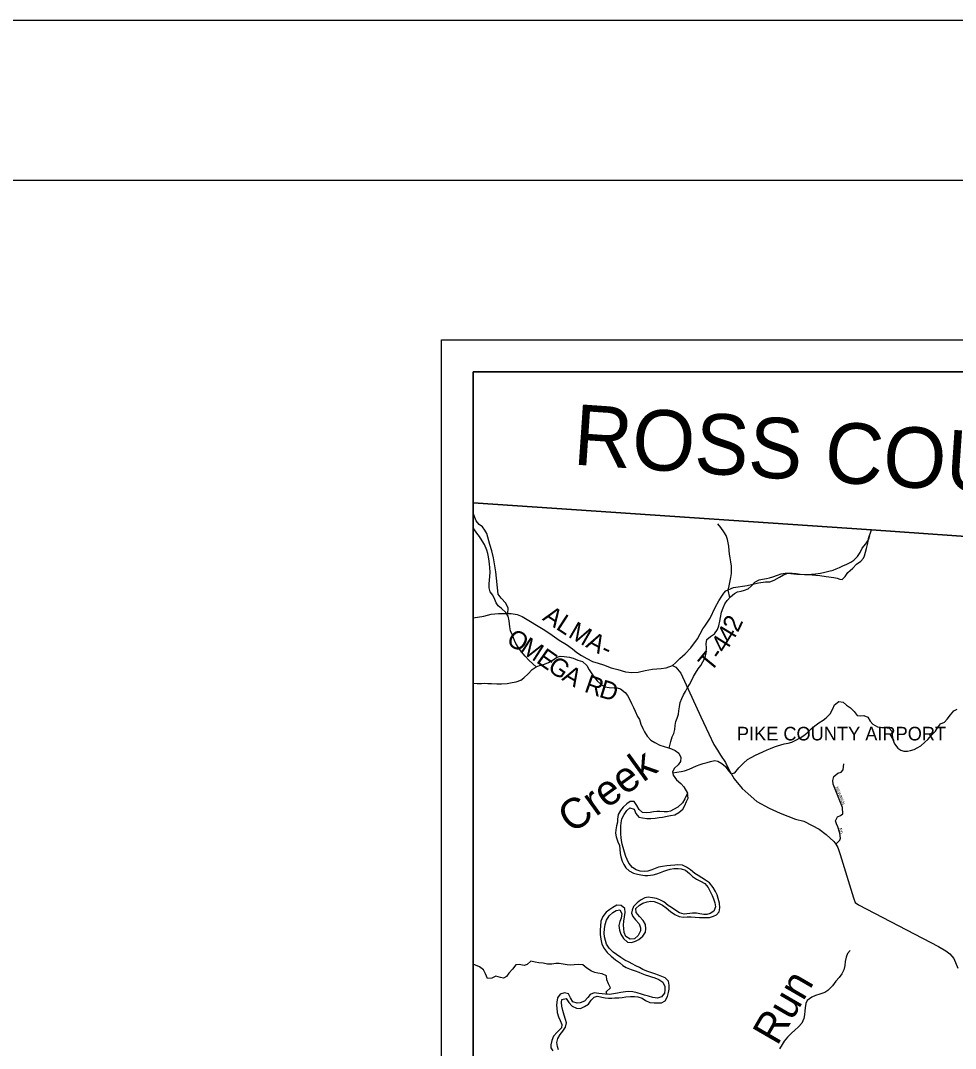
# Model space of a CAD drawing. Extents: x 0 to 34, y 0 to 22.
# Drawn here: x 22.598 to 25.527, y 18.782 to 22 of the extents above; entities that cross this region are included whole.
import ezdxf

# ---------------------------------------------------------------- set-up
doc = ezdxf.new("R2010")
doc.units = 0
for name, color, linetype in [('GM_X_Adjacent_County', 7, 'Continuous'), ('GM_X_Adjacent_County_Text', 7, 'Continuous'), ('GM_X_Airport_Text_Class_3', 7, 'Continuous'), ('GM_X_County', 7, 'Continuous'), ('GM_X_County_Road', 7, 'Continuous'), ('GM_X_County_Road_Text', 7, 'Continuous'), ('GM_X_Minor_River', 7, 'Continuous'), ('GM_X_Minor_River_Text', 7, 'Continuous'), ('GM_X_Township', 7, 'Continuous'), ('GM_X_Township_Road', 7, 'Continuous'), ('GM_X_Township_Road_Text', 7, 'Continuous'), ('GM_X_Township_Subdivision', 7, 'Continuous'), ('GM_X_Township_Subdivision_Text', 7, 'Continuous'), ('SH_Border', 7, 'Continuous'), ('SH_Cut_Line', 7, 'Continuous'), ('SH_Data', 7, 'Continuous')]:
    doc.layers.add(name, color=color, linetype=linetype)

msp = doc.modelspace()

# ---------------------------------------------------------------- linework, layer by layer
at = {"layer": 'GM_X_Adjacent_County'}
for points in [[(30.8167, 19.9966), (30.8167, 20.9), (24.0167, 20.9), (24.0167, 20.4902)], [(24.0167, 20.4902), (25.2637, 20.4053), (26.0476, 20.3502), (26.2222, 20.3325), (27.8816, 20.224), (28.5075, 20.1657), (30.3764, 20.0297), (30.5069, 20.0201), (30.8167, 19.9966)]]:
    msp.add_lwpolyline(points, dxfattribs=at)
at = {"layer": 'GM_X_County'}
for points in [[(24.0167, 20.4902), (24.0167, 14.1), (30.8167, 14.1), (30.8167, 19.9966)], [(30.8167, 19.9966), (30.5069, 20.0201), (30.3764, 20.0297), (28.5075, 20.1657), (27.8816, 20.224), (26.2222, 20.3325), (26.0476, 20.3502), (25.2637, 20.4053), (24.0167, 20.4902)]]:
    msp.add_lwpolyline(points, dxfattribs=at)
at = {"layer": 'GM_X_County_Road'}
msp.add_lwpolyline([(24.0167, 20.1298), (24.0491, 20.1354), (24.0722, 20.1414), (24.0955, 20.1436), (24.1114, 20.1436), (24.1248, 20.1434), (24.1353, 20.1433), (24.154, 20.1406), (24.1699, 20.134), (24.2409, 20.0919), (24.2635, 20.0755), (24.2854, 20.0602), (24.3084, 20.0468), (24.3269, 20.0334), (24.3412, 20.0216), (24.3556, 20.0128), (24.3726, 20.0028), (24.3903, 19.994), (24.4073, 19.9882), (24.4247, 19.9832), (24.4482, 19.9736), (24.4697, 19.9682), (24.4936, 19.9608), (24.5132, 19.9592), (24.5333, 19.9606), (24.5546, 19.9655), (24.5784, 19.9699), (24.6053, 19.9717), (24.6209, 19.9739), (24.6402, 19.9813), (24.6512, 19.9756), (24.667, 19.9569), (24.7295, 19.8204), (24.7539, 19.7675), (24.7704, 19.734), (24.782, 19.7157), (24.7914, 19.7001), (24.8061, 19.6776), (24.8177, 19.6529), (24.8338, 19.6259), (24.8587, 19.5962), (24.8771, 19.5794), (24.9047, 19.5557), (24.9436, 19.5339), (24.9776, 19.5185), (25.0256, 19.5004), (25.0517, 19.4938), (25.0785, 19.4804), (25.0996, 19.4689), (25.1219, 19.4521), (25.146, 19.4304), (25.152, 19.4216), (25.1588, 19.4117), (25.1655, 19.3896), (25.2076, 19.2532), (25.2124, 19.2391), (25.223, 19.2315), (25.4742, 19.1015), (25.4964, 19.0881), (25.5089, 19.0789), (25.5213, 19.0641), (25.5348, 19.0333)], dxfattribs=at)
at = {"layer": 'GM_X_Minor_River'}
for points in [[(24.2138, 19.9765), (24.192, 19.9965), (24.1793, 20.0103), (24.1677, 20.0234), (24.1572, 20.0379), (24.1502, 20.0494), (24.1454, 20.0597), (24.1399, 20.0757), (24.1336, 20.0898), (24.1307, 20.102), (24.1294, 20.1209), (24.1254, 20.135), (24.1187, 20.1465), (24.1052, 20.1596), (24.0947, 20.168), (24.0887, 20.1776), (24.0843, 20.1875), (24.078, 20.2009), (24.0698, 20.212), (24.0665, 20.2241), (24.0667, 20.2363), (24.0676, 20.2477), (24.0688, 20.2598), (24.069, 20.2727), (24.0688, 20.2879), (24.0674, 20.2985), (24.0664, 20.308), (24.0643, 20.3217), (24.0617, 20.3316), (24.0588, 20.3423), (24.0518, 20.3598), (24.0444, 20.3717), (24.0358, 20.385), (24.028, 20.3954), (24.0186, 20.4084), (24.0167, 20.4111)], [(24.82, 20.1938), (24.8154, 20.2168), (24.8179, 20.2308), (24.8211, 20.2456), (24.8231, 20.2566), (24.8252, 20.2691), (24.8257, 20.2789), (24.8254, 20.2922), (24.8233, 20.3055), (24.8208, 20.3181), (24.8194, 20.3291), (24.8184, 20.3405), (24.8174, 20.3546), (24.8131, 20.3751), (24.8084, 20.3881), (24.8017, 20.3999), (24.7924, 20.4126), (24.7826, 20.4248)], [(24.6299, 19.7226), (24.6352, 19.7436), (24.6395, 19.758), (24.6446, 19.7682), (24.6477, 19.7807), (24.649, 19.7932), (24.6514, 19.8057), (24.655, 19.8166), (24.6589, 19.8291), (24.6609, 19.8393), (24.6622, 19.8515), (24.665, 19.8647), (24.6697, 19.878), (24.6755, 19.8897), (24.6817, 19.8998), (24.686, 19.9097), (24.6933, 19.9217), (24.6999, 19.9327), (24.7065, 19.9466), (24.7127, 19.9572), (24.7212, 19.9704), (24.7297, 19.9813), (24.7355, 19.9922), (24.7425, 20.0058), (24.7457, 20.021), (24.7466, 20.0358), (24.7464, 20.049), (24.7484, 20.0627), (24.7595, 20.0717), (24.7721, 20.0799), (24.7818, 20.0942), (24.7857, 20.1048), (24.7893, 20.1203), (24.7909, 20.1317), (24.7942, 20.1476), (24.7989, 20.1619), (24.8047, 20.1737), (24.812, 20.1846), (24.822, 20.1962), (24.8343, 20.2067), (24.8442, 20.2112), (24.8552, 20.2141), (24.8662, 20.2166), (24.8773, 20.221), (24.8872, 20.2297), (24.8988, 20.2421), (24.9121, 20.2491), (24.9227, 20.2513), (24.9345, 20.2534), (24.9448, 20.2556), (24.9547, 20.2581), (24.9699, 20.2636), (24.9809, 20.2677), (24.9938, 20.2702), (25.0056, 20.2705), (25.0155, 20.27), (25.0283, 20.2687), (25.0401, 20.267), (25.0537, 20.2661), (25.0666, 20.266), (25.0764, 20.2666), (25.0886, 20.268), (25.1038, 20.2705), (25.1178, 20.273), (25.13, 20.2763), (25.1441, 20.2799), (25.1536, 20.2836), (25.1635, 20.288), (25.1745, 20.2928), (25.1867, 20.2984), (25.1989, 20.3043), (25.2085, 20.3107), (25.22, 20.322), (25.2281, 20.3351), (25.2351, 20.3484), (25.2462, 20.3619), (25.2547, 20.3747), (25.2591, 20.3883)], [(24.0167, 19.9261), (24.0176, 19.926), (24.029, 19.9251), (24.0426, 19.925), (24.0521, 19.9252), (24.0623, 19.9247), (24.0737, 19.9246), (24.09, 19.9237), (24.1051, 19.9231), (24.1226, 19.9244), (24.1385, 19.9273), (24.1514, 19.9302), (24.1651, 19.9353), (24.1751, 19.9428), (24.1881, 19.9548), (24.2012, 19.9687), (24.2138, 19.9765), (24.224, 19.981), (24.2392, 19.985), (24.2526, 19.9901), (24.2652, 19.9972), (24.2793, 20.0069), (24.2892, 20.0102), (24.3009, 20.0093), (24.3184, 20.0076), (24.3297, 20.0037), (24.3444, 19.9978), (24.3584, 19.9935), (24.3726, 19.9815), (24.38, 19.9674)], [(24.38, 19.9674), (24.3882, 19.9552), (24.3957, 19.9448), (24.4047, 19.9334), (24.4159, 19.9222), (24.4287, 19.9145), (24.4419, 19.9117), (24.4578, 19.9107), (24.4673, 19.9106), (24.4779, 19.9075), (24.4918, 19.8963), (24.4993, 19.8867), (24.5059, 19.8753), (24.5122, 19.8623), (24.5182, 19.8493), (24.5237, 19.8379), (24.5307, 19.8215), (24.5367, 19.8115), (24.5414, 19.7978), (24.5477, 19.7837), (24.5529, 19.7738), (24.5611, 19.7596), (24.5727, 19.7474), (24.5851, 19.74), (24.6006, 19.7319), (24.6149, 19.7279), (24.6281, 19.7232), (24.6379, 19.72), (24.6489, 19.7154), (24.6605, 19.7065), (24.6668, 19.6935), (24.6659, 19.6803), (24.6586, 19.6701), (24.6467, 19.6596), (24.6401, 19.6479), (24.6423, 19.6376), (24.6535, 19.6231), (24.6662, 19.6116), (24.676, 19.6012), (24.6872, 19.5816)], [(24.6406, 19.6455), (24.6678, 19.6487), (24.6781, 19.6516), (24.6929, 19.6568), (24.704, 19.6612), (24.7154, 19.6672), (24.7272, 19.6708), (24.7367, 19.6741), (24.7496, 19.6778), (24.7599, 19.6807), (24.7732, 19.6832), (24.783, 19.6816), (24.7951, 19.6746), (24.8063, 19.6646), (24.816, 19.6516), (24.8239, 19.642), (24.8353, 19.6449), (24.8487, 19.6607), (24.8625, 19.6754), (24.8756, 19.6866), (24.887, 19.6933), (24.9004, 19.7004), (24.9118, 19.7059), (24.924, 19.7103), (24.9373, 19.717), (24.948, 19.7207), (24.9602, 19.7259), (24.9697, 19.7299), (24.9799, 19.7325), (24.9902, 19.7354), (25.0031, 19.7383), (25.0145, 19.7412), (25.0271, 19.7471), (25.0401, 19.7542), (25.0519, 19.762), (25.0623, 19.7703), (25.0745, 19.7823), (25.086, 19.792), (25.0986, 19.8017), (25.112, 19.8096), (25.1219, 19.8174), (25.1346, 19.8302), (25.1431, 19.8449), (25.1478, 19.8581), (25.1612, 19.8686), (25.1748, 19.8658), (25.1861, 19.8569), (25.1977, 19.8488), (25.2101, 19.8369), (25.2187, 19.8247), (25.2308, 19.8238), (25.2403, 19.8248), (25.2523, 19.819), (25.2598, 19.8071), (25.2676, 19.7975), (25.2827, 19.789), (25.2959, 19.7873), (25.3065, 19.7868), (25.319, 19.7852), (25.3276, 19.7756), (25.329, 19.763), (25.3307, 19.749), (25.3362, 19.7353), (25.3459, 19.7222), (25.3557, 19.7157), (25.3655, 19.7129), (25.3765, 19.7132), (25.3864, 19.7146), (25.3974, 19.7179), (25.407, 19.7231), (25.418, 19.7298), (25.4307, 19.7406), (25.4402, 19.7496), (25.4525, 19.7643), (25.4648, 19.7755), (25.4702, 19.7857), (25.4802, 19.7981), (25.4928, 19.8033), (25.5013, 19.8131), (25.5109, 19.8266), (25.522, 19.8387), (25.5327, 19.8446)], [(24.6872, 19.5816), (24.6793, 19.5636), (24.6716, 19.5508), (24.6574, 19.5376), (24.6441, 19.5298), (24.6345, 19.5254), (24.625, 19.5232), (24.6144, 19.5226), (24.6012, 19.5235), (24.5917, 19.5236), (24.5807, 19.5226), (24.5701, 19.5212), (24.5598, 19.5198), (24.5469, 19.5211), (24.5361, 19.5307), (24.5286, 19.5429), (24.52, 19.5548), (24.5075, 19.5557), (24.498, 19.5482), (24.4865, 19.5377), (24.4773, 19.5272), (24.4699, 19.5143), (24.4682, 19.4996), (24.4681, 19.4901), (24.4654, 19.4795), (24.4626, 19.4662), (24.4624, 19.456), (24.4638, 19.445), (24.4697, 19.4293), (24.4741, 19.4175), (24.4759, 19.4057), (24.4769, 19.3921), (24.4783, 19.3818), (24.483, 19.3681), (24.4882, 19.3585), (24.4945, 19.3474), (24.505, 19.3378), (24.5182, 19.3312), (24.5311, 19.3273), (24.5413, 19.3253), (24.5541, 19.3236), (24.5636, 19.3235), (24.5803, 19.3256), (24.5917, 19.3289), (24.6031, 19.3325), (24.6138, 19.337), (24.6233, 19.3403), (24.6336, 19.3432), (24.6446, 19.345), (24.6579, 19.3456), (24.6677, 19.3447), (24.6817, 19.3404), (24.6941, 19.33), (24.7027, 19.32), (24.7155, 19.3119), (24.7287, 19.3057), (24.7418, 19.2983), (24.7519, 19.2864), (24.7601, 19.2715), (24.7649, 19.2609), (24.7693, 19.2506), (24.7734, 19.2384), (24.7755, 19.2258), (24.7704, 19.2122), (24.7582, 19.2048), (24.7479, 19.2018), (24.7384, 19.2012), (24.726, 19.2036), (24.7161, 19.2052), (24.7036, 19.2058), (24.6771, 19.203), (24.6627, 19.207), (24.6514, 19.214), (24.6371, 19.2232), (24.6274, 19.2302), (24.6131, 19.2413), (24.6006, 19.2479), (24.5908, 19.2518), (24.5784, 19.2539), (24.5644, 19.2556), (24.5541, 19.2538), (24.5404, 19.246), (24.5297, 19.2381), (24.5185, 19.2269), (24.5142, 19.2155), (24.5122, 19.2057), (24.5159, 19.1954), (24.5245, 19.1847), (24.5365, 19.1724), (24.5401, 19.1598), (24.54, 19.1499), (24.5334, 19.136), (24.5215, 19.1255), (24.5075, 19.1245), (24.4943, 19.1323), (24.4888, 19.1456), (24.4878, 19.1578), (24.4872, 19.1676), (24.4877, 19.1805), (24.4905, 19.1945), (24.4926, 19.2078)], [(24.4819, 19.2049), (24.4795, 19.1905), (24.4755, 19.1791), (24.4727, 19.1667), (24.4749, 19.1526), (24.4789, 19.14), (24.4871, 19.1259), (24.4994, 19.1151), (24.5119, 19.1138), (24.5249, 19.1182), (24.5352, 19.1234), (24.5474, 19.1332), (24.5555, 19.1464), (24.5575, 19.1562), (24.5565, 19.1703), (24.5484, 19.1825), (24.5367, 19.1948), (24.5267, 19.2074), (24.526, 19.2203), (24.5375, 19.2304), (24.5478, 19.2371), (24.5608, 19.2416), (24.5729, 19.2429), (24.5835, 19.2421), (24.5964, 19.2374), (24.6088, 19.2304), (24.6208, 19.2227), (24.6347, 19.2107), (24.6479, 19.2018), (24.6614, 19.1949), (24.6747, 19.1936), (24.6868, 19.1938), (24.6986, 19.1937), (24.7111, 19.1928), (24.7247, 19.1919), (24.7436, 19.1924), (24.7562, 19.1926), (24.7687, 19.1959), (24.7782, 19.2), (24.7871, 19.2101), (24.7891, 19.2226), (24.7877, 19.2367), (24.7841, 19.2512), (24.7801, 19.263), (24.7757, 19.2733), (24.7682, 19.2863), (24.7563, 19.3008), (24.7435, 19.3089), (24.7329, 19.3166), (24.7209, 19.324), (24.7107, 19.3302), (24.6972, 19.341), (24.6848, 19.3498), (24.6716, 19.3557), (24.6572, 19.3574), (24.6474, 19.3563), (24.6348, 19.3546), (24.6223, 19.3536), (24.6094, 19.3522), (24.5969, 19.3493), (24.5866, 19.3453), (24.5763, 19.3416), (24.5634, 19.3376), (24.5535, 19.3358), (24.5395, 19.3371), (24.5271, 19.3418), (24.5158, 19.3483), (24.5042, 19.3618), (24.499, 19.3736), (24.4949, 19.3831), (24.4902, 19.3968), (24.4858, 19.4113), (24.4833, 19.422), (24.4804, 19.433), (24.4793, 19.4429), (24.4791, 19.4528), (24.4792, 19.4657), (24.479, 19.4782), (24.4795, 19.488), (24.4823, 19.5009), (24.4889, 19.5145), (24.4974, 19.5269), (24.5073, 19.5356), (24.5202, 19.5312), (24.5253, 19.5175), (24.5346, 19.506), (24.5464, 19.504), (24.5604, 19.5019), (24.5729, 19.5018), (24.5862, 19.5035), (24.5983, 19.5053), (24.6093, 19.5067), (24.6237, 19.5092), (24.6348, 19.5113), (24.6477, 19.5138), (24.6606, 19.5209), (24.6733, 19.5314), (24.6795, 19.5427), (24.6849, 19.5552), (24.69, 19.5661), (24.6872, 19.5816)], [(24.4926, 19.2078), (24.4908, 19.2207), (24.4795, 19.2296), (24.4667, 19.2309), (24.4533, 19.2234), (24.4438, 19.2167), (24.4327, 19.2092), (24.4223, 19.1957), (24.4157, 19.1806), (24.4147, 19.1647), (24.4139, 19.1533), (24.4145, 19.1404), (24.4147, 19.1309), (24.4169, 19.1187), (24.4194, 19.1084), (24.4264, 19.0951), (24.4362, 19.0824), (24.4485, 19.0709), (24.4624, 19.0594), (24.4741, 19.0509), (24.4853, 19.042), (24.4959, 19.0355), (24.5106, 19.0292), (24.5238, 19.0249), (24.5351, 19.021), (24.5449, 19.0167), (24.5551, 19.0128), (24.5653, 19.01), (24.5751, 19.0065), (24.5853, 19.0037), (24.5974, 18.9982), (24.6102, 18.9897), (24.6161, 18.9764), (24.6167, 18.9654), (24.6151, 18.9555), (24.6066, 18.9435), (24.5933, 18.9398), (24.5789, 18.9415), (24.565, 18.9458), (24.5533, 18.949), (24.5431, 18.9522), (24.5298, 18.9561), (24.5159, 18.9593), (24.503, 18.9602), (24.4935, 18.9596), (24.4787, 18.9578), (24.4681, 18.9557), (24.4559, 18.9528), (24.4434, 18.9507), (24.4305, 18.9519), (24.4199, 18.9532), (24.4097, 18.9545), (24.3957, 18.9561), (24.3827, 18.951), (24.375, 18.9412), (24.3654, 18.9299), (24.3517, 18.9248), (24.3415, 18.9237), (24.3283, 18.9277), (24.3212, 18.9407), (24.3153, 18.9536), (24.3024, 18.9564), (24.2891, 18.9524), (24.2803, 18.9408), (24.2779, 18.9275), (24.2774, 18.918), (24.2784, 18.9078), (24.2798, 18.8948), (24.2838, 18.8815), (24.2882, 18.8701), (24.2941, 18.8571), (24.2925, 18.8469), (24.2798, 18.8334), (24.2679, 18.8202), (24.2628, 18.8074), (24.2597, 18.7937), (24.2599, 18.7843), (24.2655, 18.7747)], [(24.283, 18.7783), (24.2804, 18.7882), (24.2787, 18.8007), (24.2819, 18.8132), (24.2888, 18.826), (24.2973, 18.8366), (24.3058, 18.8486), (24.3086, 18.8623), (24.3057, 18.8729), (24.3016, 18.8862), (24.2969, 18.9007), (24.294, 18.9148), (24.2926, 18.9262), (24.2939, 18.9357), (24.3072, 18.9386), (24.3154, 18.9256), (24.3266, 18.9148), (24.3398, 18.9078), (24.3523, 18.9077), (24.3652, 18.9136), (24.3778, 18.9203), (24.3859, 18.9335), (24.3955, 18.9432), (24.405, 18.9454), (24.4292, 18.9406), (24.4406, 18.9393), (24.4501, 18.9392), (24.4603, 18.9402), (24.4721, 18.9408), (24.4827, 18.9419), (24.4948, 18.944), (24.5089, 18.945), (24.5214, 18.9445), (24.5316, 18.9436), (24.5456, 18.9396), (24.5565, 18.9327), (24.5697, 18.9261), (24.5829, 18.9251), (24.6057, 18.9249), (24.6171, 18.9312), (24.6244, 18.9444), (24.6284, 18.9576), (24.63, 18.9679), (24.6305, 18.98), (24.628, 18.9926), (24.6172, 19.0037), (24.6074, 19.0076), (24.5964, 19.0115), (24.5851, 19.0158), (24.573, 19.0198), (24.5606, 19.0237), (24.5477, 19.0292), (24.5372, 19.0354), (24.5255, 19.0412), (24.5146, 19.0474), (24.5048, 19.052), (24.4916, 19.059), (24.4788, 19.0668), (24.4649, 19.0768), (24.4551, 19.0837), (24.4424, 19.096), (24.4338, 19.1083), (24.4302, 19.1205), (24.4276, 19.1319), (24.4262, 19.1429), (24.4272, 19.1565), (24.4292, 19.1706), (24.4339, 19.1842), (24.4424, 19.1974), (24.4539, 19.2082), (24.4638, 19.2138), (24.476, 19.216), (24.4819, 19.2049)], [(25.1976, 19.0893), (25.1892, 19.0791), (25.1841, 19.0682), (25.1809, 19.0549), (25.18, 19.0421), (25.1772, 19.028), (25.1706, 19.016), (25.1625, 19.0047), (25.1518, 18.9923), (25.1418, 18.978), (25.1276, 18.9633), (25.1177, 18.9577), (25.102, 18.9522), (25.088, 18.9478), (25.0773, 18.943), (25.0628, 18.9326), (25.0581, 18.9228), (25.0561, 18.9091), (25.0556, 18.8996), (25.0543, 18.8879), (25.0523, 18.8761), (25.0461, 18.8618), (25.0357, 18.8498), (25.0242, 18.8396), (25.0135, 18.8299), (25.0012, 18.8175), (24.9908, 18.8051), (24.9839, 18.7946), (24.9758, 18.7806)], [(24.4355, 18.9514), (24.4332, 18.9591), (24.4459, 18.9715), (24.4396, 18.9841), (24.4348, 18.9974), (24.4338, 19.0096), (24.4206, 19.0162), (24.407, 19.0175), (24.3968, 19.0203), (24.387, 19.0238), (24.3723, 19.0338), (24.3595, 19.0435), (24.3463, 19.0455), (24.3323, 19.0438), (24.322, 19.0428), (24.3103, 19.0436), (24.2982, 19.0461), (24.2853, 19.0477), (24.2755, 19.0486), (24.2625, 19.0465), (24.2489, 19.0463), (24.2357, 19.0494), (24.2217, 19.0507), (24.2107, 19.052), (24.1971, 19.0556), (24.1852, 19.0455), (24.1757, 19.0418), (24.1602, 19.0446), (24.15, 19.0436), (24.1396, 19.0304), (24.1284, 19.0176), (24.1207, 19.0079), (24.1112, 19.0019), (24.1014, 19.0043), (24.0874, 19.0083), (24.0744, 19.0019), (24.0608, 19.001), (24.0549, 19.0155), (24.049, 19.028), (24.0358, 19.0381), (24.023, 19.0424), (24.0167, 19.0462)]]:
    msp.add_lwpolyline(points, dxfattribs=at)
at = {"layer": 'GM_X_Township'}
msp.add_line((24.0167, 20.4902), (24.0167, 17.2008), dxfattribs=at)
msp.add_lwpolyline([(30.8167, 19.9966), (30.5069, 20.0201), (30.3764, 20.0297), (28.5075, 20.1657), (27.8816, 20.224), (26.2222, 20.3325), (26.0476, 20.3502), (25.2637, 20.4053), (24.0167, 20.4902)], dxfattribs=at)
at = {"layer": 'GM_X_Township_Road'}
for points in [[(24.1248, 20.1434), (24.1257, 20.1608), (24.1186, 20.1757), (24.1039, 20.1921), (24.0949, 20.2046), (24.0869, 20.2745), (24.0795, 20.3182), (24.0743, 20.3402), (24.0688, 20.3603), (24.0585, 20.3941), (24.0526, 20.4049), (24.0458, 20.4147), (24.035, 20.4222), (24.0254, 20.4341), (24.021, 20.4442), (24.0174, 20.4555), (24.0167, 20.4607)], [(24.6402, 19.9813), (24.6497, 19.9889), (24.6638, 20.0029), (24.6806, 20.018), (24.6984, 20.0361), (24.7187, 20.0644), (24.7355, 20.0955), (24.7416, 20.1046), (24.7588, 20.1288), (24.7741, 20.1625), (24.7859, 20.1833), (24.7947, 20.1984), (24.8012, 20.2071), (24.8077, 20.2147), (24.832, 20.2252), (24.8744, 20.2318), (24.9101, 20.2403), (24.9321, 20.2433), (24.9457, 20.2432), (24.959, 20.2484), (24.9757, 20.2578), (24.9886, 20.265), (25.0019, 20.2699), (25.0303, 20.2667), (25.0655, 20.2661), (25.1018, 20.2625), (25.1219, 20.2598), (25.1457, 20.257), (25.1563, 20.2539), (25.1646, 20.2512), (25.1715, 20.2504), (25.181, 20.2595), (25.1901, 20.272), (25.197, 20.2788), (25.2054, 20.2852), (25.2173, 20.2981), (25.2304, 20.3077), (25.2385, 20.3175), (25.2418, 20.3241), (25.2447, 20.336), (25.2478, 20.3472), (25.252, 20.3642), (25.2544, 20.3787), (25.2637, 20.4053)]]:
    msp.add_lwpolyline(points, dxfattribs=at)
at = {"layer": 'GM_X_Township_Subdivision'}
msp.add_lwpolyline([(25.152, 19.4216), (25.165, 19.4337), (25.1665, 19.4409), (25.1647, 19.4561), (25.1583, 19.4758), (25.1546, 19.4857), (25.1516, 19.4945), (25.157, 19.5077), (25.1669, 19.5115), (25.1737, 19.5167), (25.173, 19.5369), (25.1443, 19.6095), (25.1424, 19.6209), (25.1455, 19.6338), (25.1588, 19.6436), (25.1694, 19.6473), (25.1752, 19.6549), (25.1775, 19.6727)], dxfattribs=at)
at = {"layer": 'SH_Border'}
msp.add_lwpolyline([(2, 21.5), (33.5, 21.5), (33.5, 0.5), (2, 0.5)], close=True, dxfattribs=at)
at = {"layer": 'SH_Cut_Line'}
msp.add_lwpolyline([(0, 0), (34, 0), (34, 22), (0, 22)], close=True, dxfattribs=at)
at = {"layer": 'SH_Data'}
for points in [[(23.9167, 21), (30.9167, 21), (30.9167, 14), (23.9167, 14)], [(24.0167, 20.9), (30.8167, 20.9), (30.8167, 14.1), (24.0167, 14.1)]]:
    msp.add_lwpolyline(points, close=True, dxfattribs=at)

# ---------------------------------------------------------------- texts
at = {"layer": 'GM_X_Adjacent_County_Text'}
msp.add_text('ROSS COUNTY', height=0.189394, rotation=356.0927, dxfattribs=at).set_placement((24.3263, 20.6104))
at = {"layer": 'GM_X_Airport_Text_Class_3'}
msp.add_text('PIKE COUNTY AIRPORT', height=0.042614, rotation=0, dxfattribs=at).set_placement((24.8422, 19.7464))
at = {"layer": 'GM_X_County_Road_Text'}
for s, rotation, p in [('A', 326.312, (24.2305, 20.125)), ('L', 326.989, (24.2727, 20.0969)), ('M', 330.0316, (24.3111, 20.072)), ('O', 329.2624, (24.117, 20.0506)), ('A', 331.6923, (24.3661, 20.0403)), ('M', 327.2955, (24.1595, 20.0253)), ('E', 325.0273, (24.2109, 19.9923)), ('-', 334.2406, (24.4126, 20.0154)), ('G', 325.3654, (24.246, 19.9678)), ('A', 329.8166, (24.2912, 19.9368)), ('R', 340.7365, (24.3612, 19.8997)), ('D', 343.0214, (24.4076, 19.8836))]:
    msp.add_text(s, height=0.0568, rotation=rotation, dxfattribs=at).set_placement(p)
at = {"layer": 'GM_X_Minor_River_Text'}
for s, rotation, p in [('Creek', 35.8824, (24.326, 19.4529)), ('Run', 59.8794, (24.9688, 18.7882))]:
    msp.add_text(s, height=0.09472, rotation=rotation, dxfattribs=at).set_placement(p)
at = {"layer": 'GM_X_Township_Road_Text'}
for s, rotation, p in [('2', 64.2713, (24.8452, 20.0823)), ('4', 58.64, (24.8241, 20.0471)), ('4', 57.7969, (24.805, 20.0167)), ('T', 50.4841, (24.7601, 19.9583)), ('-', 55.4774, (24.7904, 19.9954))]:
    msp.add_text(s, height=0.0568, rotation=rotation, dxfattribs=at).set_placement(p)
at = {"layer": 'GM_X_Township_Subdivision_Text'}
for s, rotation, p in [('NEWMAN', 291.7995, (25.1505, 19.5996)), ('RD', 274.1991, (25.1622, 19.4724))]:
    msp.add_text(s, height=0.00947, rotation=rotation, dxfattribs=at).set_placement(p)

doc.saveas('drawing.dxf')
